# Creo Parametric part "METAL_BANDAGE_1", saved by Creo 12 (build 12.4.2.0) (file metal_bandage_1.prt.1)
Units: Custom; MM, KILOGRAM, SECS

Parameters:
  PTC_WM_ITERATION = "0"
  PTC_WM_VERSION = "-.0"
  PTC_WM_LIFECYCLE_STATE = "In Work"
  PTC_WM_LIFECYCLE = "MO_CADDocument"
  PTC_WM_CREATED_BY = "Maximilian Roepper (Z0017RMS: MO)"
  PTC_WM_CREATED_ON = "18-Sep-26 11:36:42 AM"
  PTC_WM_MODIFIED_BY = "Maximilian Roepper (Z0017RMS: MO)"
  PTC_WM_MODIFIED_ON = "18-Sep-26 11:36:46 AM"
  PDMLINKNUMBER = "PDM000071455314"
  PTC_WM_NAME = "metal_bandage_1.prt"
  PTC_WM_NUMBER = "PDM000071455314"

Other parameters: WEIGHT, WEIGHT_FACTOR, WEIGHT_ADD, _MASS_TEMP, _DIFF_TEMP, MC_ERRORS, SUPPLIER

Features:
  1. coordinate system
  2. datum plane "PRT_YZ"
  3. datum plane "PRT_XY"
  4. datum plane "PRT_XZ"
  5. coordinate system
  6. datum axis
  7. datum axis
  8. datum axis
  9. coordinate system
  10. imported feature

Other named items: PRT, SIEMENS_MO, DRW_VIEW_ORG, PRT_X, PRT_Y, PRT_Z, CS0, ROUGH_GROB

Layers: 00_STD_CSYS-KSYS, 01_STD_PLANES-EBENEN, 02_STD_AXES-ACHSEN, 03_STD_CSYS-KSYS, 24_IMPORT_FEAT-IMPORT_KE

Surfaces: 84 plane, 10 cylinder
